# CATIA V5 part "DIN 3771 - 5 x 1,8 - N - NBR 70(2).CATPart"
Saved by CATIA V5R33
Part number: DIN 3771 - 5 x 1,8 - N - NBR 70(2)
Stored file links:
  C:\Users\Ryzen5700u\Desktop\robot_cicloidale_singolo\Assieme_robot_cicloidale_singolo\DIN 3771 - 5 x 1,8 - N - NBR 70(2).CATPart

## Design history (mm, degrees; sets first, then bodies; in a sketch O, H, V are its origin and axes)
Body1 "Solido1" (main body)
  Solid1: solid without history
